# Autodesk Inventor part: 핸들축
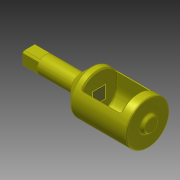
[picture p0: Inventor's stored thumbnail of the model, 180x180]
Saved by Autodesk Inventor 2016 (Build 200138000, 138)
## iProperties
Created: 2018-01
Part Number: 핸들축
Material: 강철, 연강
Document SubType Name: Modeling
Designer: mduedu
Density: 1 g/cm^3
Appearance: 노란색
Author: mduedu
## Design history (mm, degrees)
sketch "스케치1"
  geometry: L1 (0, 0)-(-109, 0); L2 (-46, -7.5)-(0, -7.5); L3 (0, -7.5)-(0, 0); L4 (-106, -19)-(-46, -19); L5 (-46, -19)-(-46, -7.5); L6 (-106, -7.5)-(-106, -19); L7 (-109, -5.768)-(-106, -7.5); L8 (-109, -5.768)-(-109, 0)
  constraints: 16 end point, 2 parallel, 1 horizontal, 1 vertical
  dimensions: "d8" = 15 diameter of L2 L1; "d43" = 46 distance between parallel lines of L3 L5; "d47" = 60 distance between parallel lines of L5 L6; "d63" = 3 distance between parallel lines of L6 L8; "d77" = 38 diameter of L4 L1; "d78" = 15 diameter of L6.start L1; "d79" = 30 deg angle of L1 L7
revolve "회전1" sketch "스케치1" stored, may be unused: angle "d9" = 90 deg
sketch "스케치4"
  geometry: L1 (-6, -6)-(-4.5, -6); L2 (6, -6)-(6, -4.5); L3 (6, 6)-(4.5, 6); L4 (-6, 6)-(-6, 4.5); L5 (-6, -6)-(6, 6); L6 (6, -6)-(-6, 6); L7 (-4.5, 6)-(-6, 6); L8 (-6, 4.5)-(-6, -4.5); L9 (-6, -4.5)-(-6, -6); L10 (-4.5, -6)-(4.5, -6); L11 (4.5, -6)-(6, -6); L12 (6, -4.5)-(6, 4.5); L13 (6, 4.5)-(6, 6); L14 (4.5, 6)-(-4.5, 6); C1 r 7.5 at (0, 0) reference; 2 further points
  constraints: 28 end point, 18 parallel, 9 perpendicular, 3 horizontal, 2 midpoint, 1 coincident, 11 other
  dimensions: "d20" = 12 distance of L4.start L3.start; "d21" = 12 distance of L3.start L2.start (= d20)
extrude "돌출2" cut sketch "스케치4" distance "d22" = 15; taper "d23" = 0 deg
chamfer "모따기2" distance "d24" = 1; stored, may be unused: second distance "d25" = 2, angle "d26" = 45 deg
sketch "스케치5"
  geometry: 2 further points
  constraints: 1 coincident
hole "구멍1" sketch "스케치5" at (5, 4.153) diameter "d27" = 2.459; stored, may be unused: countersink angle "d31" = 90 deg, drill point angle "d33" = 120 deg; dims "d28" = 6.9, "d29" = 4, "d30" = 2, "d32" = 8.4
node "작업 평면1"
sketch "스케치9"
  geometry: L1 (10, 4.153)-(10, 15.815); L2 (-20, 4.153)-(-20, 15.815); A1 r 15 centre (-5, 4.153) between (-20, 4.153) and (10, 4.153); A2 r 19 centre (-5, 4.153) between (10, 15.815) and (-20, 15.815) reference; 1 further point
  constraints: 4 end point, 4 point on circle, 2 tangent, 1 centre point, 1 coincident, 1 concentric, 1 parallel, 1 vertical
  dimensions: "d76" = 4 radial gap between concentric circles of A2 A1
extrude "돌출4" cut sketch "스케치9" distance "d73" = 34; taper "d74" = 0 deg
chamfer "모따기3" distance "d44" = 10; stored, may be unused: second distance "d45" = 2, angle "d46" = 45 deg
fillet "모깎기4" dims "d80" = 1
chamfer "모따기5" distance "d81" = 1; stored, may be unused: second distance "d82" = 2, angle "d83" = 45 deg
node "솔리드1"
other parameters: "d75" = -64
